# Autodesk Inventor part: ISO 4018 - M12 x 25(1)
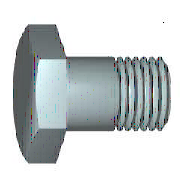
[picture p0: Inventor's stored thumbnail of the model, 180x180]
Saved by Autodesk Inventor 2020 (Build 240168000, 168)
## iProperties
Created: 2019-01
Part Number: ISO 4018 - M12 x 25(1)
Material: Ocel
Description: Šrouby se šestihrannou hlavou se závitem k hlavě. Výrobní třída C
Document SubType Name: Modeling
Standard: ISO 4018
Designer: doma
Standard Revision: Fourth edition 2011-04-01
Standards Organization: ISO
Language: cs-CZ
Size Designation: M12 x 25
Categories: <MemberInstance><Categories><Category DisplayName="Spojovací materiál" InternalName="e4da775c-781d-43d5-af7c-5136215cf5a6" Mnemonic="FSTN"><Category DisplayName
Density: 7.85 g/cm^3
Appearance: Plech
IsCustomPart: 0
Author: doma
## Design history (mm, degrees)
node "WorkPlane1"
node "WorkPoint1"
node "MSC_A1"
node "MSC_PF1"
node "MSC_PT1"
body "Solid1"
node "Náčrt1"
sketch "Náčrt2"
  geometry: L1 (-9, 5.196)-(-9, -5.196); L2 (0, 10.392)-(-9, 5.196); L3 (9, 5.196)-(0, 10.392); L4 (9, -5.196)-(9, 5.196); L5 (0, -10.392)-(9, -5.196); L6 (-9, -5.196)-(0, -10.392); C1 r 9 at (0, 0); 1 further point
  constraints: 12 end point, 6 tangent, 2 parallel, 2 vertical, 1 centre point
  dimensions: "d1" = 18 diameter of C1 (= ParS); "d29" = 0 distance of point (0, 0) C1.centre; "d30" = 0 distance of C1.centre point (0, 0)
extrude "Vysunutí1" new body sketch "Náčrt2" distance "d6" = 7.5 (= ParK); taper "d7" = 0 deg
revolve "Rotace1" stored, may be unused: angle "d14" = 360 deg
revolve "Rotace2" stored, may be unused: angle "d21" = 360 deg
chamfer "Zkosení1" distance "d22" = 0.875 (= 0.5 x PTC); stored, may be unused: second distance "d23" = 0.875 (= 0.5 x PTC), angle "d39" = 45 deg
fillet "Zaoblení1" dims "d24" = 0.6 (= r)
feature "Závit1" dims "d32" = 0, "b" = 21.5 (= NLG - 2 x PTC)
sketch "Náčrt3"
  geometry: L1 (9, 7.5)-(10.492, 7.5); L2 (10.492, 6.639)-(9, 7.5); L3 (10.492, 7.5)-(10.492, 6.639); L4 (0, -1.5)-(0, 9) reference; L5 (10.392, 0)-(10.392, 7.5) reference
  constraints: 6 end point, 1 horizontal, 1 vertical
  dimensions: "d25" = 0.1 distance between parallel lines of L5 L3; "d26" = 0 distance from line of L5.end L1; "d27" = 60 deg angle of L3 L2; "d28" = 9 distance from line of L4 L1.start (= 0.5 x ParS)
sketch "Náčrt4"
  geometry: L1 (0, -25)-(0, 0); L2 (-6, -25)-(0, -25); L3 (-6, 0)-(-6, -25); L4 (0, 0)-(-6, 0); L5 (0, -25)-(0, 0); L6 (-7.2, 0)-(1.2, 0) reference; L7 (0, -30)-(0, 5) reference
  constraints: 10 end point, 2 horizontal, 2 vertical
  dimensions: "d18" = 6 distance of L1.start L2.start (= 0.5 x NND); "d20" = 25 distance of L3.start L2.start (= NLG); "d33" = 0 distance between parallel lines of L7 L1; "d34" = 0 distance between parallel lines of L6 L4
other parameters: "NND" = 12 [user parameter; used in 2 equation terms], "NLG" = 25 [user parameter; used in 2 equation terms], "PTC" = 1.75 [user parameter; used in 3 equation terms], "ParK" = 7.5 [user parameter; used in 1 equation term], "ParS" = 18 [user parameter; used in 3 equation terms], "msp_es" = 10.39261 (= 0.577367 x ParS) [user parameter], "r" = 0.6 [user parameter; used in 1 equation term], "d2" = 15 (derived), "d4" = 17.32102 (derived), "d8" = 15 (derived), "d10" = 0 (derived), "d12" = 30 deg (derived), "d15" = 0 (derived), "d37" = 0, "d38" = 0, "d40" = 0, "d41" = 0, "d42" = 0, "THREADDIA" = 12 (= NND) [user parameter]
